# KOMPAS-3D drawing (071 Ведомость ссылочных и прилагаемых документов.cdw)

Referenced files in C:\Documents and Settings\nastya\Рабочий стол\Проекты г.Альметьевкс\: 4 Ведомость ссылочных и прилагаемых документов.cdw
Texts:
  ПСПД-0000-2015
  Ведомость ссылочных и  прилагаемых документов
  Zver
  Microsoft
  СП 41-101-95
  ГОСТ 21.1101-2009
  СНиП 41-02-2003
  ГОСТ 21.110-95
  ГОСТ Р 51649-2000
  Ссылочные документы
  Проектирование тепловых пунктов
  Основные требования к проектной и
  рабочей документации
  Тепловые сети
  Правила выполнения спецификации оборудования,
  изделий и материалов
  Условные обозначения элементов санитарно-
  технических систем
  Условные обозначения трубопроводов
  Праивла учета тепловой энергии и теплоносителя
  Степени защиты, обеспечиваемые оболочками (КОД IP)
  Теплосчетчики для водяных систем теплоснабжения.
  Общие технические условия.
  Тепловычислитель ТВ7.
  ГИП
  Пров.
  Разраб.
  Ведомость ссылочных и
  прилагаемых документов
  ЗАО "ПромСервис"
  Руководство по эксплуатации.
  Прилагаемые документы
  Свидетельство СРО №034-ДПСРО от 14.05.2013 г.
  ГОСТ 21.205-93
  ГОСТ 21.206-93
  ГОСТ 14256-96
  РЭПР.407290.007 РЭ
  ArialMT
  Технические условия на проектирование и монтаж узла учета тепловой энергии.
  Преобразователи расхода электромагнитные
  ЭМИР-ПРАМЕР-550.
  Приказ Минстроя РФ №99/пр от 17.03.2014
  №1034 от 18.11.2013г
  СНиП 3.05.07-85
  СНиП 23-01-99*
  СНиП 2.04.05-91
  Методика осуществления коммерческого учета тепловой энергии и теплоносителя
  Правила коммерческого учета тепловой энергии, теплоносителя
  Системы автоматизации
  Строительная климатология
  Отопление, вентиляция и кондиционирование.
  Ведомость ОК рабочих чертежей. Ведомость ссылочных и прилагаемых док-тов. Первый лист. ГОСТ Р 21.1101-2009 Ф2
  Лит-Масса-Масштаб
  Материал-Предприятие
  Title Specification
  Body Specification ( left align )
  Body Specificaton ( centered )
  Подпись лица, копировавшего чертеж
  Обозначение формата листа
  Инв. № подл.
  Подп. и дата
  Взам. инв. №
  Инвентарный номер подлинника
  Подпись принявшего подлинник в отдел технической документации
  Инвентарный номер подлинника, взамен которого выпущен данный подлинник
  Согласовано
  Подпись
  Изм.
  Кол.уч.
  Лист
  № док.
  Подп.
  Дата
  Листов
  Стадия
  Порядковый номер изменения документа
  Количество изменяемых участков
  Обозначение разрешения
  Наименование документа
  Порядковый номер листа
  Количество листов документа
  Наименование (различительный индекс) предприятия, выпускающего документ
  Таблица ведомости
  Таблица согласований
  Ведомость ОК рабочих чертежей. Ведомость ссылочных и прилагаемых док-ов. Первый лист. ГОСТ Р 21.1101-2009 Ф2
Dimensions and other numbers on the sheet: 1:1; 06-03/11-ПК-ОВ-; 4213-022-12560879 РЭ; 1; 4 листа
